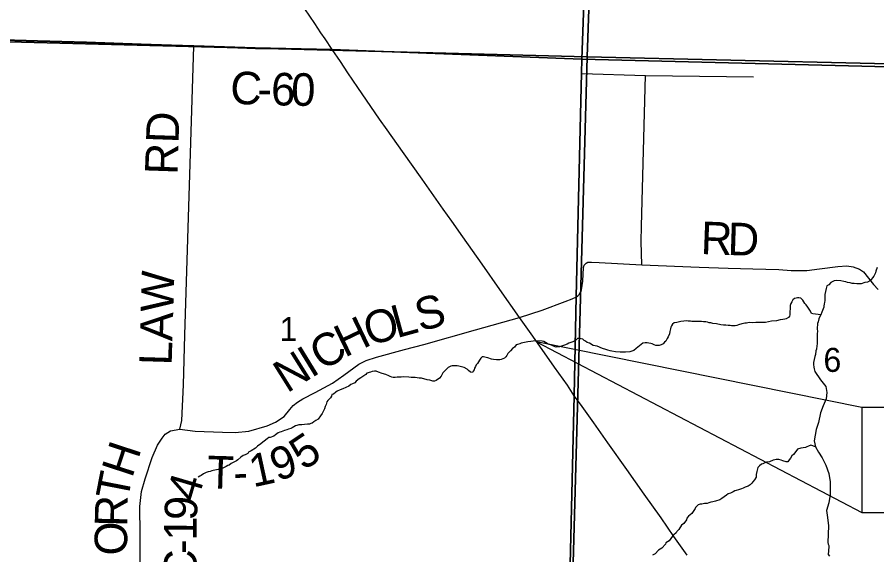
# Model space of a CAD drawing. Extents: x 0 to 34, y 0 to 22.
# Drawn here: x 5.004 to 6.504, y 16.804 to 17.741 of the extents above; entities that cross this region are included whole.
import ezdxf

# ---------------------------------------------------------------- set-up
doc = ezdxf.new("R2010")
doc.units = 0
for name, color, linetype in [('Default', 7, 'Continuous'), ('GM_X_County_Road', 7, 'Continuous'), ('GM_X_County_Road_Text', 7, 'Continuous'), ('GM_X_Minor_River', 7, 'Continuous'), ('GM_X_Section', 7, 'Continuous'), ('GM_X_Section_Text', 7, 'Continuous'), ('GM_X_Township_Road', 7, 'Continuous'), ('GM_X_Township_Road_Text', 7, 'Continuous'), ('GM_X_US_Route', 7, 'Continuous'), ('SH_Text', 7, 'Continuous')]:
    doc.layers.add(name, color=color, linetype=linetype)

msp = doc.modelspace()

# ---------------------------------------------------------------- linework, layer by layer
at = {"layer": 'Default'}
for points in [[(4.98, 17.7015), (5.0396, 17.6997), (5.1253, 17.6972), (5.2207, 17.6942), (5.2737, 17.6923), (5.3125, 17.691), (5.4195, 17.6873), (5.5532, 17.6849), (5.9893, 17.6676), (6.0568, 19.5343), (6.0632, 19.7108), (6.0696, 20.0002), (6.0777, 20.3704), (6.08, 20.4768), (6.0809, 20.5156), (6.0839, 20.7194), (6.0871, 20.9), (2.1, 20.9)], [(2.1, 14.1), (5.898, 14.1), (5.9162, 14.6505), (5.9251, 14.9951), (5.9419, 15.65), (5.9423, 15.6675), (5.945, 15.7379), (5.9475, 15.8049), (5.9496, 15.8622), (5.9546, 15.9939), (5.9579, 16.0817), (5.9658, 16.6637), (5.9756, 17.0812), (5.9796, 17.2537), (5.9888, 17.6433), (5.9893, 17.6676), (5.5532, 17.6849), (5.4195, 17.6873), (5.3125, 17.691), (5.2737, 17.6923), (5.2207, 17.6942), (5.1253, 17.6972), (5.0396, 17.6997), (4.98, 17.7015)]]:
    msp.add_lwpolyline(points, dxfattribs=at)
for points in [[(8.9, 17.6104), (8.9, 20.9), (6.0871, 20.9), (6.0839, 20.7194), (6.0809, 20.5156), (6.08, 20.4768), (6.0777, 20.3704), (6.0696, 20.0002), (6.0632, 19.7108), (6.0568, 19.5343), (5.9893, 17.6676), (6.9889, 17.643), (7.0308, 17.6406), (8.0065, 17.6245)], [(5.898, 14.1), (8.9, 14.1), (8.9, 17.6104), (8.0065, 17.6245), (7.0308, 17.6406), (6.9889, 17.643), (5.9893, 17.6676), (5.9888, 17.6433), (5.9796, 17.2537), (5.9756, 17.0812), (5.9658, 16.6637), (5.9579, 16.0817), (5.9546, 15.9939), (5.9496, 15.8622), (5.9475, 15.8049), (5.945, 15.7379), (5.9423, 15.6675), (5.9419, 15.65), (5.9251, 14.9951), (5.9162, 14.6505)]]:
    msp.add_lwpolyline(points, close=True, dxfattribs=at)
at = {"layer": 'GM_X_County_Road'}
for points in [[(5.2098, 16.4792), (5.218, 16.6912), (5.2186, 16.8394), (5.2183, 16.888), (5.2211, 16.9137), (5.2276, 16.9358), (5.2397, 16.9731), (5.2493, 16.9947), (5.2573, 17.0071), (5.2626, 17.0139), (5.2715, 17.0198), (5.2878, 17.0229), (5.2916, 17.0379), (5.2945, 17.1001), (5.297, 17.1864), (5.3127, 17.6904)], [(5.3127, 17.6904), (5.4198, 17.6867), (5.5535, 17.6844)]]:
    msp.add_lwpolyline(points, dxfattribs=at)
at = {"layer": 'GM_X_Minor_River'}
for points in [[(6.5046, 17.3046), (6.5022, 17.2982), (6.5017, 17.2952), (6.4989, 17.2896), (6.4962, 17.2866), (6.4927, 17.2818), (6.4877, 17.2792), (6.4827, 17.2782), (6.4766, 17.2761), (6.4743, 17.2758), (6.469, 17.2759), (6.4644, 17.2764), (6.4606, 17.2765), (6.4576, 17.2777), (6.4527, 17.2786), (6.4496, 17.2794), (6.4462, 17.2803), (6.4409, 17.2815), (6.4333, 17.2817), (6.4295, 17.281), (6.4261, 17.2796), (6.4234, 17.2782), (6.4202, 17.2744), (6.4168, 17.2726), (6.4152, 17.2681), (6.4134, 17.2575), (6.4129, 17.2537), (6.4132, 17.2495), (6.4131, 17.2465), (6.4127, 17.2442), (6.4122, 17.2405), (6.4114, 17.2378), (6.4113, 17.2352), (6.4093, 17.2295), (6.4081, 17.2265), (6.4061, 17.222), (6.4041, 17.2179), (6.4025, 17.2152), (6.4013, 17.21), (6.4004, 17.2066), (6.3998, 17.1975), (6.4001, 17.1929), (6.4, 17.1895), (6.3996, 17.1713), (6.3991, 17.1682), (6.3986, 17.1622), (6.3974, 17.1592), (6.3969, 17.1531), (6.3957, 17.1493), (6.3935, 17.1387), (6.3931, 17.1353), (6.3941, 17.1307), (6.3944, 17.1281), (6.3951, 17.1254)], [(6.4061, 17.222), (6.3924, 17.2235), (6.3898, 17.2243), (6.388, 17.2285), (6.3832, 17.2351), (6.3806, 17.2393), (6.3784, 17.2417), (6.3747, 17.2475), (6.371, 17.251), (6.368, 17.2518), (6.3657, 17.2515), (6.3634, 17.2512), (6.36, 17.2505), (6.3573, 17.2479), (6.3553, 17.2449), (6.3541, 17.2415), (6.3525, 17.2385), (6.3521, 17.2222), (6.3517, 17.2199), (6.3497, 17.2173), (6.3458, 17.2151), (6.3432, 17.2144), (6.3397, 17.2138), (6.3352, 17.2131), (6.3286, 17.2114), (6.3203, 17.2108), (6.3096, 17.2088), (6.3012, 17.2086), (6.2925, 17.2085), (6.2867, 17.2082), (6.281, 17.2084), (6.2765, 17.2077), (6.2738, 17.2074), (6.2711, 17.2067), (6.2681, 17.2064), (6.2623, 17.2043), (6.2596, 17.2032), (6.2566, 17.2029), (6.2543, 17.2026), (6.2505, 17.2027), (6.2478, 17.2031), (6.2444, 17.2032), (6.2406, 17.2037), (6.2364, 17.2042), (6.2319, 17.2047), (6.224, 17.2064), (6.2179, 17.2069), (6.2145, 17.2078), (6.2114, 17.2082), (6.2084, 17.209), (6.2054, 17.2095), (6.2016, 17.21), (6.1978, 17.2101), (6.1814, 17.2105), (6.1788, 17.2109), (6.175, 17.211), (6.172, 17.2115), (6.1674, 17.2112), (6.1617, 17.2106), (6.1552, 17.2085), (6.1506, 17.2078), (6.1475, 17.206), (6.1455, 17.2026), (6.1447, 17.2004), (6.1439, 17.1977), (6.143, 17.1928), (6.1422, 17.189), (6.1401, 17.1834), (6.1382, 17.1808), (6.1358, 17.1763), (6.1335, 17.1744), (6.1311, 17.1715), (6.1276, 17.1696), (6.1242, 17.1686), (6.1185, 17.1687), (6.1155, 17.1696), (6.1117, 17.1712), (6.1094, 17.172), (6.1064, 17.1728), (6.1034, 17.1733), (6.0996, 17.1734), (6.0954, 17.1724), (6.0838, 17.1631), (6.0799, 17.1598), (6.073, 17.1577), (6.0654, 17.1571), (6.0559, 17.157), (6.0482, 17.1572), (6.0414, 17.1589), (6.0384, 17.1593), (6.0346, 17.1602), (6.0312, 17.1618), (6.0252, 17.1635), (6.0158, 17.1671), (6.009, 17.1688), (6.0026, 17.1724), (5.9988, 17.174)], [(5.9988, 17.174), (5.9954, 17.176), (5.9932, 17.1775), (5.991, 17.1795), (5.986, 17.1808), (5.9815, 17.1805), (5.9784, 17.1775), (5.9737, 17.175), (5.9703, 17.1739), (5.9668, 17.1725), (5.9634, 17.1711), (5.9592, 17.1693), (5.9553, 17.1679), (5.9503, 17.1661), (5.9469, 17.1662), (5.9442, 17.1658), (5.9397, 17.1671), (5.9363, 17.1691), (5.9307, 17.1707), (5.9258, 17.1739), (5.9232, 17.1755), (5.9198, 17.1763), (5.9084, 17.1766), (5.9004, 17.1757), (5.895, 17.1747), (5.892, 17.1744), (5.8866, 17.173), (5.8835, 17.1723), (5.8812, 17.1712), (5.877, 17.1702), (5.8747, 17.1695), (5.8716, 17.1654), (5.8685, 17.1632), (5.865, 17.1591), (5.8623, 17.1569), (5.8603, 17.1543), (5.8587, 17.1513), (5.8568, 17.149), (5.8544, 17.1464), (5.8514, 17.1454), (5.8487, 17.1443), (5.846, 17.1436), (5.8403, 17.1434), (5.8354, 17.1439), (5.8316, 17.1447), (5.8255, 17.1468), (5.8225, 17.1476), (5.8176, 17.1485), (5.8153, 17.1485), (5.813, 17.1467), (5.8106, 17.143), (5.8074, 17.1373), (5.8051, 17.1347), (5.8039, 17.1321), (5.8023, 17.1291), (5.8015, 17.1261), (5.7999, 17.1235), (5.7983, 17.1212), (5.7953, 17.1221), (5.7916, 17.1252), (5.7893, 17.1272), (5.7841, 17.1299), (5.7792, 17.1312), (5.7769, 17.132), (5.7746, 17.1325), (5.772, 17.1329), (5.7685, 17.133), (5.7655, 17.1331), (5.7628, 17.1331), (5.7605, 17.1324), (5.7563, 17.1303), (5.7536, 17.128), (5.7489, 17.1232), (5.7466, 17.121), (5.7438, 17.115), (5.7407, 17.1113), (5.7353, 17.1076), (5.7322, 17.1065), (5.7295, 17.1066), (5.7239, 17.1079), (5.7193, 17.1088), (5.7095, 17.1113), (5.7053, 17.1118), (5.6985, 17.1127), (5.6916, 17.1129), (5.6875, 17.1134), (5.6783, 17.1136), (5.6742, 17.1133), (5.6707, 17.1134), (5.6669, 17.1131), (5.6639, 17.1128), (5.6601, 17.1129), (5.6578, 17.1133), (5.6548, 17.1146), (5.6525, 17.1154), (5.6473, 17.1178), (5.6408, 17.1198), (5.6348, 17.1223), (5.6303, 17.1239), (5.6276, 17.124), (5.6238, 17.1233)], [(6.3951, 17.1254), (6.3957, 17.1229), (6.4058, 17.1084), (6.4151, 17.0968), (6.4168, 17.0866), (6.4154, 17.0756), (6.4103, 17.0635), (6.4055, 17.0511), (6.4021, 17.0344), (6.3981, 17.0223), (6.396, 17.0121), (6.3947, 17.0022), (6.3968, 16.992), (6.4023, 16.9824), (6.4086, 16.9724), (6.4148, 16.9601), (6.4199, 16.9456), (6.4223, 16.9307), (6.4225, 16.9209), (6.4226, 16.9087), (6.4201, 16.8943), (6.416, 16.8807), (6.4177, 16.8685), (6.4193, 16.8541), (6.4182, 16.8251)], [(5.6238, 17.1233), (5.6204, 17.1219), (5.6142, 17.1201), (5.6127, 17.1179), (5.6038, 17.1124), (5.6007, 17.1102), (5.5956, 17.1061), (5.5933, 17.1032), (5.5891, 17.1014), (5.5864, 17.1003), (5.5829, 17.0977), (5.5775, 17.0952), (5.5725, 17.0931), (5.5679, 17.0913), (5.5625, 17.0887), (5.5602, 17.0873), (5.556, 17.0836), (5.5533, 17.0829), (5.5525, 17.0803), (5.5509, 17.0773), (5.5462, 17.0724), (5.5446, 17.0702), (5.543, 17.0657), (5.5414, 17.0623), (5.5405, 17.0581), (5.5393, 17.0559), (5.5365, 17.0499), (5.5334, 17.0458), (5.5291, 17.0398), (5.5252, 17.038), (5.5218, 17.0354), (5.519, 17.0332), (5.5164, 17.0325), (5.5141, 17.0315), (5.5106, 17.0312), (5.5057, 17.0309), (5.5007, 17.0303), (5.4954, 17.03), (5.4919, 17.0293), (5.4896, 17.0286), (5.4869, 17.0264), (5.4842, 17.025), (5.4816, 17.0239), (5.4773, 17.0225), (5.4746, 17.0214), (5.4708, 17.0204), (5.4647, 17.0179), (5.4624, 17.0175), (5.4593, 17.0165), (5.4551, 17.0128), (5.452, 17.0106), (5.4454, 17.0081), (5.4431, 17.0078), (5.4401, 17.0059), (5.435, 17.0015), (5.4327, 16.9997), (5.4292, 16.9971), (5.4234, 16.9931), (5.4203, 16.9897), (5.4122, 16.985), (5.4076, 16.9824), (5.4068, 16.9802), (5.4018, 16.9776), (5.3983, 16.9766), (5.3944, 16.974), (5.3894, 16.9692), (5.3871, 16.9674), (5.3824, 16.9648), (5.3778, 16.9627), (5.374, 16.9601), (5.3717, 16.959), (5.369, 16.9576), (5.3667, 16.9561), (5.3628, 16.9547), (5.3548, 16.9522), (5.3464, 16.9505), (5.3441, 16.9502), (5.341, 16.9488), (5.3376, 16.9481), (5.3341, 16.947), (5.3318, 16.946), (5.3291, 16.9445), (5.3253, 16.9419), (5.3229, 16.9409), (5.3202, 16.9387)], [(6.3968, 16.992), (6.3887, 16.9949), (6.3848, 16.9927), (6.3817, 16.9916), (6.3794, 16.9909), (6.371, 16.9896), (6.3657, 16.9875), (6.3625, 16.9838), (6.3582, 16.9786), (6.3555, 16.9763), (6.3535, 16.9722), (6.3508, 16.9689), (6.3488, 16.9655), (6.3458, 16.9656), (6.3397, 16.9676), (6.3371, 16.9688), (6.3329, 16.9697), (6.3284, 16.9698), (6.3261, 16.9691), (6.323, 16.9684), (6.3165, 16.9659), (6.3115, 16.9649), (6.3085, 16.9638), (6.305, 16.9624), (6.3027, 16.9617), (6.2992, 16.9584), (6.2961, 16.9558), (6.2949, 16.9513), (6.2948, 16.9486), (6.2935, 16.9433), (6.2931, 16.9392), (6.2907, 16.9343), (6.2875, 16.9309), (6.2856, 16.9283), (6.2829, 16.9257), (6.2794, 16.9232), (6.2744, 16.9214), (6.2705, 16.9196), (6.2675, 16.9185), (6.2625, 16.9167), (6.2587, 16.9157), (6.256, 16.915), (6.2533, 16.9135), (6.2487, 16.911), (6.2445, 16.9096), (6.2418, 16.9078), (6.2336, 16.9015), (6.2298, 16.8993), (6.2225, 16.8968), (6.2175, 16.8958), (6.2145, 16.8951), (6.211, 16.8941), (6.2079, 16.893), (6.2034, 16.8928), (6.1988, 16.8921), (6.1957, 16.8918), (6.1919, 16.8904), (6.1876, 16.8863), (6.1868, 16.8841), (6.1813, 16.8754), (6.1755, 16.871), (6.1727, 16.8673), (6.1719, 16.8647), (6.1672, 16.8583), (6.1633, 16.855), (6.1586, 16.8479), (6.1547, 16.8442), (6.1539, 16.8416), (6.15, 16.8382), (6.1477, 16.836), (6.1418, 16.8278), (6.136, 16.8242), (6.1352, 16.8219), (6.1286, 16.8152), (6.1228, 16.8119), (6.1169, 16.8053), (6.1127, 16.8027)], [(6.4182, 16.8251), (6.4189, 16.8221), (6.42, 16.8198), (6.4203, 16.8167), (6.4194, 16.8114), (6.4193, 16.8088), (6.4189, 16.8061), (6.4189, 16.8038), (6.4214, 16.8011)]]:
    msp.add_lwpolyline(points, dxfattribs=at)
at = {"layer": 'GM_X_Section'}
for points in [[(5.0264, 18.7096), (6.0336, 18.6715), (5.9983, 17.6719), (4.989, 17.6982)], [(6.0336, 18.6715), (7.008, 18.6577), (7.0009, 17.6487), (5.9983, 17.6719)], [(4.989, 17.6982), (5.9983, 17.6719), (5.9708, 16.6629), (4.9556, 16.6985)], [(5.9983, 17.6719), (7.0009, 17.6487), (7.0384, 17.6474), (7.0136, 16.6391), (5.9708, 16.6629)]]:
    msp.add_lwpolyline(points, close=True, dxfattribs=at)
at = {"layer": 'GM_X_Township_Road'}
for points in [[(4.1124, 17.7392), (4.1136, 17.7311), (4.1167, 17.728), (4.1241, 17.7263), (4.1356, 17.7258), (4.1971, 17.724), (4.2772, 17.7217), (4.4205, 17.7175), (4.5062, 17.715), (4.6239, 17.7116), (4.6737, 17.7097), (4.7632, 17.7079), (4.9047, 17.7034), (4.9802, 17.701), (5.0399, 17.6991), (5.1255, 17.6967), (5.2209, 17.6936), (5.2739, 17.6918), (5.3127, 17.6904)], [(5.989, 17.6428), (6.1003, 17.6394), (6.289, 17.6372)], [(6.094, 17.3094), (6.0929, 17.35), (6.0934, 17.3767), (6.1003, 17.6394)], [(5.9821, 17.2554), (5.9851, 17.2583), (5.9885, 17.2656), (5.9912, 17.2808), (5.9919, 17.3045), (5.9934, 17.3087), (5.9959, 17.3111)], [(5.9959, 17.3111), (5.9971, 17.3123), (5.9999, 17.3138), (6.0061, 17.3141), (6.0194, 17.3135), (6.094, 17.3094), (6.1939, 17.3054), (6.2445, 17.3036), (6.2877, 17.3021), (6.3328, 17.301), (6.3543, 17.2993), (6.3816, 17.2991), (6.4038, 17.3021), (6.4358, 17.3065), (6.4516, 17.3076), (6.4626, 17.3059), (6.4739, 17.3014), (6.4807, 17.2968), (6.498, 17.2747), (6.5059, 17.266)], [(5.8805, 17.2175), (5.9198, 17.2302), (5.9604, 17.2455), (5.9726, 17.2499), (5.9799, 17.2532), (5.9821, 17.2554)], [(5.2878, 17.0229), (5.3145, 17.0192), (5.3627, 17.0172), (5.3844, 17.0168), (5.4084, 17.0194), (5.4405, 17.0283), (5.4551, 17.0348), (5.47, 17.0446), (5.4799, 17.0568), (5.486, 17.0638), (5.493, 17.0696), (5.5023, 17.0755), (5.5241, 17.0863), (5.5544, 17.1029), (5.5741, 17.1169), (5.5913, 17.1296), (5.6001, 17.136), (5.6128, 17.1422), (5.6312, 17.148), (5.6797, 17.1614), (5.7136, 17.1704), (5.804, 17.1959), (5.8805, 17.2175)]]:
    msp.add_lwpolyline(points, dxfattribs=at)
at = {"layer": 'GM_X_US_Route'}
for points in [[(5.5535, 17.6844), (5.5416, 17.7031), (5.534, 17.714), (5.5233, 17.7302), (5.5061, 17.7554), (5.4715, 17.8075), (5.44, 17.8535), (5.4133, 17.8934), (5.4006, 17.9118), (5.3731, 17.9519), (5.3399, 18.0013), (5.3154, 18.0393), (5.282, 18.0871), (5.2557, 18.1266), (5.2258, 18.1701), (5.2228, 18.1747), (5.2211, 18.1772)], [(5.6498, 17.5444), (5.6366, 17.5633), (5.5987, 17.6182), (5.5813, 17.6437), (5.5681, 17.6639), (5.5535, 17.6844)], [(5.8805, 17.2175), (5.8461, 17.2663), (5.8154, 17.3105), (5.7819, 17.3579), (5.7625, 17.3855), (5.7476, 17.406), (5.7105, 17.4584), (5.6762, 17.5067), (5.6498, 17.5444)], [(6.1731, 16.8029), (6.1498, 16.8356), (6.1275, 16.8678), (6.0982, 16.9092), (6.0679, 16.9523), (6.0347, 16.9988), (6.0103, 17.0336), (5.987, 17.066), (5.9758, 17.0807), (5.9642, 17.0995), (5.9418, 17.1308), (5.924, 17.1559), (5.9011, 17.1887), (5.8805, 17.2175)]]:
    msp.add_lwpolyline(points, dxfattribs=at)
at = {"layer": 'SH_Text'}
for p, q in [((6.4777, 17.0606), (5.9103, 17.1747)), ((5.9103, 17.1747), (6.4777, 16.8774))]:
    msp.add_line(p, q, dxfattribs=at)
msp.add_lwpolyline([(6.9407, 17.0606), (6.4777, 17.0606), (6.4777, 16.8774), (6.9407, 16.8774)], close=True, dxfattribs=at)

# ---------------------------------------------------------------- texts
at = {"layer": 'GM_X_County_Road_Text'}
for s, height, rotation, p in [('C', 0.0568, 357.1145, (5.3749, 17.5905)), ('6', 0.0568, 358.8967, (5.4468, 17.5875)), ('0', 0.0568, 359.0403, (5.4819, 17.5868)), ('-', 0.0568, 358.4251, (5.4229, 17.5881)), ('RD', 0.05682, 88.0252, (5.2838, 17.4657)), ('LAW', 0.05682, 88.2825, (5.2737, 17.1334)), ('H', 0.0568, 71.9043, (5.2046, 16.9361)), ('T', 0.0568, 78.9607, (5.1969, 16.8962)), ('4', 0.0568, 73.4817, (5.3187, 16.8939)), ('R', 0.0568, 88.9041, (5.1963, 16.8521)), ('9', 0.0568, 86.945, (5.3174, 16.8624)), ('O', 0.0568, 89.9781, (5.1962, 16.8024)), ('1', 0.0568, 89.8543, (5.3173, 16.8282)), ('-', 0.0568, 89.9727, (5.3173, 16.8049)), ('C', 0.0568, 89.9971, (5.3173, 16.7582))]:
    msp.add_text(s, height=height, rotation=rotation, dxfattribs=at).set_placement(p)
at = {"layer": 'GM_X_Section_Text'}
for s, p in [('1', (5.4619, 17.1762)), ('6', (6.4107, 17.1225))]:
    msp.add_text(s, height=0.0419, rotation=0, dxfattribs=at).set_placement(p)
at = {"layer": 'GM_X_Township_Road_Text'}
for s, rotation, p in [('R', 357.9388, (6.1961, 17.3281)), ('D', 358.1536, (6.2429, 17.3264)), ('S', 15.3793, (5.7072, 17.1924)), ('O', 15.6955, (5.6182, 17.1676)), ('L', 15.3764, (5.6663, 17.1811)), ('H', 25.6641, (5.5756, 17.1469)), ('C', 31.4303, (5.5371, 17.1232)), ('N', 32.0996, (5.475, 17.0846)), ('I', 31.4986, (5.5172, 17.1111)), ('5', 33.7131, (5.5041, 16.9496)), ('9', 20.3289, (5.4584, 16.9309)), ('T', 358.3412, (5.3351, 16.9197)), ('1', 12.2852, (5.4159, 16.921)), ('-', 2.853, (5.3825, 16.9185))]:
    msp.add_text(s, height=0.0568, rotation=rotation, dxfattribs=at).set_placement(p)

doc.saveas('drawing.dxf')
